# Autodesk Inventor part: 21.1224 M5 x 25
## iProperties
Created: 2006-02
Part Number: 21.1224 M5 x 25
Material: Steel, Mild
Description: Cylinder Head Cap Screw
Document SubType Name: Modeling
Standard: DIN 7984
Designer: Andy Moles
Standards Organization: DIN
Language: en-US
Size Designation: M5 x 25
Categories: <MemberInstance><Categories><Category DisplayName="Fasteners" InternalName="e4da775c-781d-43d5-af7c-5136215cf5a6" Mnemonic="FSTN"><Category DisplayName="Bolts"
Density: 7.86 g/cm^3
Mass: 5.20504 g
Surface Area: 6.19161 cm^2
Volume: 0.662219 cm^3
Author: Andy Moles
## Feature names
1. Body [Revolution]
2. Slot [Extrusion]
3. Fillet1
4. Chamfer1
